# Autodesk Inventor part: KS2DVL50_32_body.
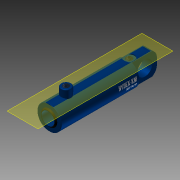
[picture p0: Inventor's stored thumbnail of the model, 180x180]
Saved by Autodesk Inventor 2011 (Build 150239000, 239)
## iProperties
Created: 2010-11
Document SubType Name: Modeling
Designer: TB
Mass: 405.061 g
Surface Area: 916.939 cm^2
Volume: 405.061 cm^3
Density: 1 g/cm^3
Author: TB
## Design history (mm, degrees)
sketch "Sketch2"
  geometry: L1 (-35, -3)-(-35, 3); L2 (-35, -9)-(-35, 9); L3 (-35, 0)-(-35, 30); L4 (-35, 30)-(-224, 30); L5 (-224, 30)-(-224, 30); L6 (-224, 30)-(-229, 30); L7 (-229, 30)-(-229, 20); L8 (-229, 20)-(-232, 17); L9 (-232, 17)-(-232, 16); L10 (-232, 16)-(-186, 16); L11 (-186, 16)-(-186, 25); L12 (-186, 25)-(-49, 25); L13 (-49, 25)-(-49, 0); L14 (-49, 0)-(-35, 0); L15 (-49, 0)-(-148.421, 0); L16 (-35, 9)-(-32, 12) reference; L17 (-32, 12)-(-35, 12) reference; L18 (-35, 12)-(-35, 9) reference; L19 (-32, 12)-(-35, 9) reference; L20 (-32, 12)-(-35, 12) reference; L21 (-35, 9)-(-35, 12) reference; L22 (-35, 9)-(-32, 12) reference; 1 further point
  constraints: 44 end point, 8 perpendicular, 6 parallel, 5 collinear, 2 horizontal, 2 vertical, 1 coincident, 1 midpoint, 1 point on line, 10 other
  dimensions: "DiaY" = 60 diameter of L4 L15; "DiaI" = 50 diameter of L12 L15; "d4" = 1 distance of L8.end L9.end; "d5" = 45 deg angle of L10 L8; "d6" = 3 distance between parallel lines of L7 L9; "DiaStang" = 32 diameter of L10 L15; "RindDia" = 60 diameter of L6 L15; "RingLengde" = 5 distance of L5.end L6.end; "RingTykk" = 43 distance between parallel lines of L11 L7; "KroppLengde" = 194 distance between parallel lines of L7 L3 (derived); "BunnTykkelse" = 14 distance between parallel lines of L13 L3
revolve "Kropp" sketch "Sketch2" stored, may be unused: angle "d13" = 90 deg
sketch "Sketch3"
  geometry: L1 (-49, -25)-(-49, 25) reference; L2 (-49, 0.01)-(-149, 0.01); L3 (-149, -0.01)-(-49, -0.01); A1 r 0.01 centre (-149, 0) between (-149, 0.01) and (-149, -0.01); A2 r 0.01 centre (-49, 0) between (-49, -0.01) and (-49, 0.01); 2 further points
  constraints: 4 end point, 4 point on circle, 4 tangent, 2 centre point, 1 coincident, 1 midpoint, 1 parallel, 1 perpendicular
  dimensions: "d17" = 0.01 radius of A2; "d18" = 100 distance of L2.start L2.end (= Slaglengde)
feature "BaneTransitionalConstraint" sketch "Sketch3" dims "d19" = 2, "d20" = 0
sketch "Sketch6"
  geometry: L1 (-42, 0)-(42, 0) reference; L2 (9.367, 28.5)-(-9.367, 28.5); L3 (30, 0)-(30, 31.248); L4 (-30, 0)-(-30, -18.451); A1 r 30 centre (0, 0) between (9.367, 28.5) and (-9.367, 28.5) reference; 1 further point
  constraints: 6 end point, 4 point on circle, 2 tangent
  dimensions: "d30" = 28.5 distance from line of A1.centre L2 (computed from DiaY); "d31" = 0 deg angle of L1 L2 (computed from Vinkel_Plussport); "d37" = 90 deg angle of L2 L3; "d38" = 90 deg angle of L2 L4
  node "Projected Loop3"
workplane "Work Plane5"
sketch "Sketch7"
  geometry: L1 (9.367, -278.4)-(9.367, 46.4) reference; L2 (-19.633, -35)-(38.367, -35) reference; C1 r 12.5 at (9.367, -52.5); 1 further point
  constraints: 1 centre point, 1 point on line
  dimensions: "PortDia" = 25 diameter of C1
extrude "Extrusion2" cut sketch "Sketch7" stored distance "d34" = 1.5; taper "d35" = 0 deg
workplane "Work Plane7"
sketch "Sketch4" dims "d142" = 12.20713
  geometry: L1 (-16.68, -40)-(-16.68, -78.777); L2 (-16.68, -78.777)-(16.68, -78.777); L3 (16.68, -78.777)-(16.68, -40); L4 (16.68, -40)-(-16.68, -40); L5 (-40.643, -40)-(0, -40); L6 (-29, -35)-(29, -35) reference; L7 (0, -35)-(0, -40); 3 further points
  constraints: 4 end point, 2 midpoint, 1 perpendicular, 2 other
  dimensions: "d40" = 5 distance of L7.start L5.end
emboss "Emboss1" sketch "Sketch4" dims "d4" = 1, "d5" = 45 deg, "d6" = 3, "d22" = 0.2, "d23" = 0, "DiaI" = 50, "DiaY" = 60, "RindDia" = 60, "DiaStang" = 32, "RingTykk" = 43, "RingLengde" = 5, "KroppLengde" = 194 (derived), "BunnTykkelse" = 14
workplane "Work Plane8"
sketch "Sketch8"
  geometry: L1 (-29, -35)-(29, -35) reference; L2 (0, -35)-(0, -40); L3 (-5.906, -110.587)-(-5.906, -40); L4 (-5.906, -40)-(5.906, -40); L5 (5.906, -40)-(5.906, -110.587); L6 (5.906, -110.587)-(-5.906, -110.587); 3 further points
  constraints: 2 end point, 2 midpoint, 1 perpendicular, 2 other
  dimensions: "d42" = 5 distance of L2.start L2.end
emboss "Emboss2" sketch "Sketch8" dims "d4" = 1, "d5" = 45 deg, "d6" = 3, "d43" = 0.2, "d44" = 0, "DiaI" = 50, "DiaY" = 60, "RindDia" = 60, "DiaStang" = 32, "RingTykk" = 43, "RingLengde" = 5, "KroppLengde" = 194 (derived), "BunnTykkelse" = 14
sketch "Sketch9"
  geometry: A1 r 12.5 centre (9.367, -52.5) between (0, -60.776) and (18.735, -60.776) reference; 1 further point
hole "Hole1" sketch "Sketch9" at (9.367, -52.5) diameter "d45" = 14.95; stored, may be unused: countersink angle "d49" = 82 deg, drill point angle "d51" = 118 deg; dims "d46" = 6, "d47" = 3.023, "d48" = 2, "d50" = 15
workplane "Work Plane9"
sketch "Sketch10"
  geometry: L1 (-42, 0)-(42, 0) reference; L2 (0, 30)-(13.136, 30); L3 (0, 30)-(0, 31.79); L4 (12.5, 27.272)-(12.5, 48); L5 (12.5, 48)-(0, 48); L6 (0, 48)-(0, 30); L7 (0, 30)-(12.5, 27.272); C1 r 30 at (0, 0) reference; A1 r 30 centre (0, 0) between (0, 30) and (12.5, 27.272); 1 further point
  constraints: 12 end point, 4 perpendicular, 2 concentric, 2 point on circle, 1 centre point, 1 point on line, 1 tangent
  dimensions: "d53" = 0 deg angle of L1 L2 (computed from Vinkel_Minusport); "d54" = 25 diameter of L4 L3; "d55" = 18 distance between parallel lines of L2 L5
revolve "Revolution2" sketch "Sketch10" stored, may be unused: angle "d56" = 90 deg
hole "Hole2" diameter "d59" = 14.95; stored, may be unused: countersink angle "d63" = 82 deg, drill point angle "d65" = 118 deg; dims "d57" = 10, "d58" = 10, "d60" = 6, "d61" = 3.023, "d62" = 2, "d64" = 14
fillet "Fillet1" dims "d66" = 2
sketch "Sketch15"
  geometry: L1 (12, -27.495)-(12, 27.495); L2 (-12, -27.495)-(-12, 27.495); A1 r 30 centre (0, 0) between (12, -27.495) and (-12, -27.495) reference; A2 r 29.998 centre (0, 0) between (12, 27.493) and (-12, 27.493); A3 r 29.998 centre (0, 0) between (-12, -27.493) and (12, -27.493)
  constraints: 8 point on circle, 4 end point, 4 point on line, 2 centre point
  dimensions: "d95" = 12 distance from line of L1 A1.centre; "d96" = 12 distance from line of A1.centre L2
extrude "Extrusion6" join sketch "Sketch15" distance "d97" = 62; taper "d98" = 0 deg
sketch "Sketch16"
  geometry: L1 (-35, 29.998)-(27, 29.998) reference; L2 (-35, -29.998)-(27, -29.998) reference; L3 (-228, -30)-(-35, -30) reference; L4 (-228, 30)-(-35, 30) reference; L5 (-35, 29.998)-(27, 29.998) reference; L6 (27, 29.998)-(27, 27.493) reference; L7 (27, -27.493)-(27, 27.493) reference; L8 (-279.911, 0)-(83.467, 0) reference; L9 (5.002, 29.998)-(27, 29.998); L10 (27, 29.998)-(27, 8); A1 r 21.998 centre (5.002, 8) between (27, 8) and (5.002, 29.998); 2 further points
  constraints: 4 end point, 4 tangent, 2 point on circle, 2 point on line, 1 centre point, 1 collinear, 1 perpendicular
  dimensions: "d137" = 8 distance from line of L10.end L8
extrude "Extrusion7" cut sketch "Sketch16" stored distance "d101" = 24; taper "d102" = 0 deg
mirror "Mirror1"
sketch "Sketch20"
  geometry: L1 (-35, 29.998)-(27, 29.998) reference; L2 (27, -27.493)-(27, 27.493) reference; L3 (27, 29.998)-(27, 27.493) reference; L4 (-47.543, 0)-(40.26, 0) reference; L5 (21.344, 15.366)-(2.962, 25.979); L6 (2.962, 25.979)-(-4, 29.998); A1 r 12.207 centre (15.24, 4.794) between (27, 8.069) and (21.344, 15.366); A2 r 30 centre (-12.038, -0.002) between (2.962, 25.979) and (-12.038, 29.998); 2 further points
  constraints: 4 end point, 4 point on circle, 3 point on line, 3 tangent, 2 centre point, 1 collinear, 1 midpoint
  dimensions: "d139" = 8.06884 distance from line of A1.start L4; "d140" = 22.66455 distance from line of L2 point (4.335, 0); "d141" = 30 deg angle of L1 L6; "d142" = 12.20713 radius of A1; "d143" = 30 radius of A2
extrude "Extrusion10" cut sketch "Sketch20" stored distance "d144" = 10; taper "d145" = 0 deg
mirror "Mirror2"
sketch "Sketch17"
  geometry: L1 (54.986, 0)-(0, 0) reference; L2 (27.493, -248.8)-(27.493, 113.8) reference; C1 r 18.5 at (27.493, 32); 1 further point
  constraints: 1 centre point, 1 point on line
  dimensions: "d103" = 37 diameter of C1; "d125" = 32 distance from line of C1.centre L1
extrude "Extrusion8" cut sketch "Sketch17" distance "d104" = 24; taper "d105" = 0 deg
pattern_circular "Circular Pattern1 Only Subsea" dims "d108" = 180 deg (derived)
workplane "Work Plane11"
sketch "Sketch18"
  geometry: L1 (0, -58.8)-(0, 9.8) reference; L2 (25, -49)-(-25, -49) reference; C1 r 12.5 at (0, -30); 1 further point
  constraints: 1 centre point
  dimensions: "DiaForsenkPlussPort" = 25 diameter of C1; "PlassPlussport" = 19 distance from line of L2 C1.centre
extrude "Extrusion9" cut sketch "Sketch18" stored distance "d113" = 10; taper "d114" = 0 deg
sketch "Sketch19"
  geometry: 8 further points
  constraints: 1 other
hole "Hole3" sketch "Sketch19" at (0, -30) diameter "d115" = 14.95; stored, may be unused: countersink angle "d119" = 90 deg, drill point angle "d121" = 118 deg; dims "d116" = 6, "d117" = 4, "d118" = 2, "d120" = 14.5
pattern_circular "Circular Pattern2 Only Subsea" dims angle "d123" = 360 deg
body "Solid1"
chamfer "Chamfer" distance "Chamfer" = 1; stored, may be unused: second distance "d15" = 2, angle "d16" = 45 deg
node "Projected Loop2"
body "Srf1"
node "Projected Loop4"
node "Projected Loop5"
node "Projected Loop10"
other parameters: "Slaglengde" = 100, "Forlengelse_rør" = 0, "Vinkel_Plussport" = 0 [user parameter; used in 1 equation term], "Vinkel_Minusport" = 0, "d32" = 90 deg, "d39" = 90 deg, "d41" = 90 deg, "PortMinusPlass" = -42, "Minusport2" = 180 deg, "ForsenkningPlussPort" = 28.2 (derived)
